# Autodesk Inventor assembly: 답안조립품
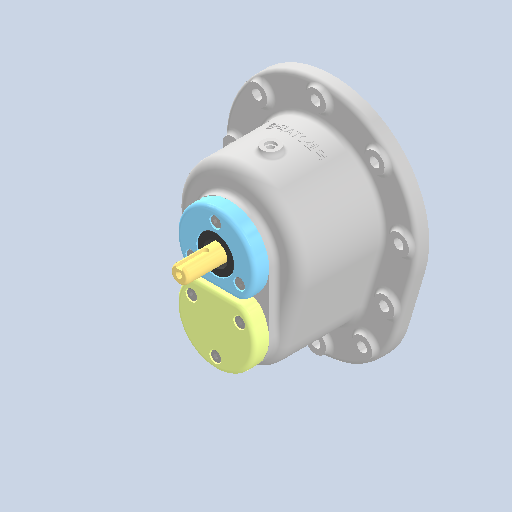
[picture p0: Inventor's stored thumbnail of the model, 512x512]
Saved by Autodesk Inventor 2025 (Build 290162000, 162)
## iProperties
Created: 2026-08
Part Number: 답안조립품
Document SubType Name: Assembly
Designer: KDI
Author: KDI
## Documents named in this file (14)
- C:\Users\KDI\Desktop\660803V1003\답안조립품.iam
- C:\Users\KDI\Desktop\660803V1003\본체\본체.ipt
- C:\Users\KDI\Desktop\660803V1003\축\축.ipt
- C:\Users\KDI\Desktop\660803V1003\평행 키 4x4x12\평행 키 4x4x12.ipt
- C:\Users\KDI\Desktop\660803V1003\깊은 홈 볼 베어링 6001\깊은 홈 볼 베어링 6001.ipt
- C:\Users\KDI\Desktop\660803V1003\C형 멈춤링 구멍용 28\C형 멈춤링 구멍용 28.ipt
- C:\Users\KDI\Desktop\660803V1003\C형 멈춤링 축용 12\C형 멈춤링 축용 12.ipt
- C:\Users\KDI\Desktop\660803V1003\스퍼 기어\스퍼 기어.ipt
- C:\Users\KDI\Desktop\660803V1003\칼라\칼라.ipt
- C:\Users\KDI\Desktop\660803V1003\기어 축\기어 축.ipt
- C:\Users\KDI\Desktop\660803V1003\상부 커버\상부 커버.ipt
- C:\Users\KDI\Desktop\660803V1003\하부 커버\하부 커버.ipt
- C:\Users\KDI\Desktop\660803V1003\오일 실 12 25 7\오일 실 12 25 7.ipt
- C:\Users\KDI\Desktop\660803V1003\6각 구멍붙이 볼트 M4x10\6각 구멍붙이 볼트 M4x10.ipt
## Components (10 placed, 4 different names)
1. C형 멈춤링 구멍용 28:1
2. C형 멈춤링 축용 12:1
3. C형 멈춤링 축용 12:2
4. 하부 커버:1
5. 6각 구멍붙이 볼트 M4x10:1
6. 6각 구멍붙이 볼트 M4x10:2
7. 6각 구멍붙이 볼트 M4x10:5
8. 6각 구멍붙이 볼트 M4x10:6
9. 6각 구멍붙이 볼트 M4x10:7
10. 6각 구멍붙이 볼트 M4x10:8
